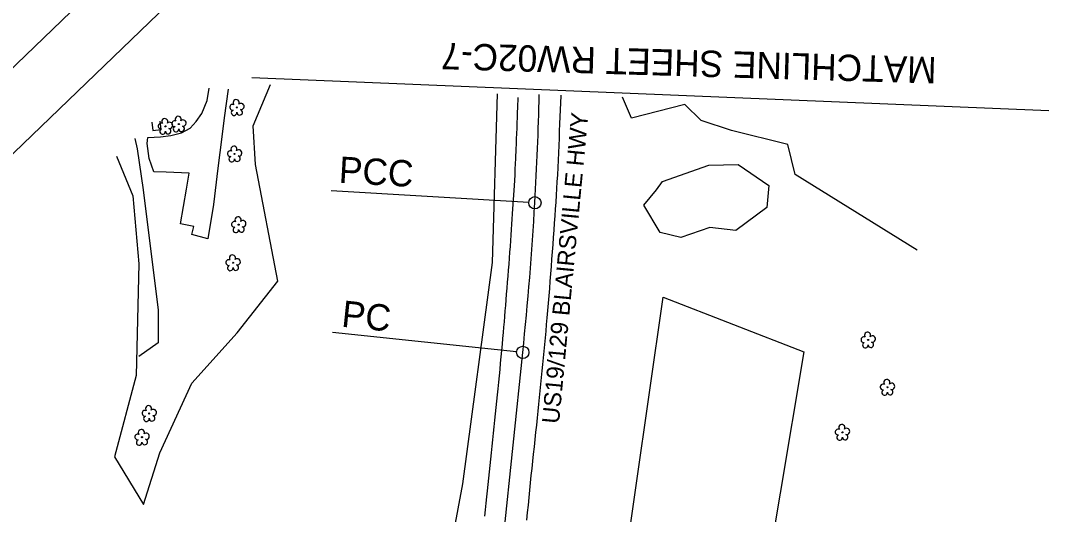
# Model space of a CAD drawing. Extents: x 473158 to 477500, y 500738 to 505114.
# Drawn here: x 474209 to 474845, y 504160 to 504459 of the extents above; entities that cross this region are included whole.
import ezdxf

# ---------------------------------------------------------------- set-up
doc = ezdxf.new("R2010")
doc.units = 0
for name, color, linetype in [('CTL Sheet Border CELL', 7, 'Continuous'), ('Exist Horizontal Alignment', 7, 'Continuous'), ('Exist Other Culture Area Outline', 7, 'Continuous'), ('Exist Roads EOP', 7, 'Continuous'), ('Exist Roads EOP Text', 7, 'Continuous'), ('Exist Roads Soil', 7, 'Continuous'), ('Exist Vegetation Hedge Row', 7, 'Continuous'), ('Exist Vegetation Tree CELL', 7, 'Continuous'), ('Exist Vegetation Woods Line', 7, 'Continuous'), ('Matchline', 7, 'Continuous'), ('Matchline Text', 7, 'Continuous'), ('Sheet Plot Border Outside CELL', 7, 'Continuous')]:
    doc.layers.add(name, color=color, linetype=linetype)

msp = doc.modelspace()

# ---------------------------------------------------------------- linework, layer by layer
at = {"layer": 'CTL Sheet Border CELL'}
msp.add_lwpolyline([(473224.2, 503436.31), (475527.63, 501042.56), (477203.24, 502654.95), (474899.8, 505048.7)], close=True, dxfattribs=at)
at = {"layer": 'Exist Horizontal Alignment'}
for p, q in [((474516.91, 504349.14), (474397.07, 504356.05)), ((474509.58, 504258.53), (474397.71, 504270.18)), ((474477.6, 503915.15), (474513.31, 504258.14))]:
    msp.add_line(p, q, dxfattribs=at)
for centre in [(474520.65, 504348.92), (474513.31, 504258.14)]:
    msp.add_circle(centre, 3.75, dxfattribs=at)
for centre, radius, start, end in [((472536.78, 504463.34), 1987.17, 356.69911, 358.59373), ((472549.42, 504462.61), 1974.51, 354.05611, 356.69911)]:
    msp.add_arc(centre, radius, start, end, dxfattribs=at)
at = {"layer": 'Exist Other Culture Area Outline'}
msp.add_lwpolyline([(474288.04, 504397.8), (474288.69, 504392.76), (474293.65, 504393.31), (474293.1, 504398.33)], dxfattribs=at)
at = {"layer": 'Exist Roads EOP'}
for points in [[(474490.23, 504158.74), (474490.63, 504162.67), (474491.02, 504166.55), (474491.42, 504170.39), (474491.82, 504174.23), (474492.22, 504178.05), (474492.62, 504181.87), (474493.02, 504185.69), (474493.43, 504189.53), (474493.84, 504193.39), (474494.25, 504197.27), (474494.66, 504201.18), (474495.08, 504205.1), (474495.51, 504209.03), (474495.94, 504212.99), (474496.37, 504216.93), (474496.79, 504220.82), (474497.2, 504224.68), (474497.59, 504228.49), (474497.98, 504232.29), (474498.37, 504236.11), (474498.75, 504239.96), (474499.13, 504243.84), (474499.5, 504247.72), (474499.87, 504251.59), (474500.24, 504255.44), (474500.6, 504259.28), (474500.95, 504263.03), (474501.28, 504266.64), (474501.59, 504270.1), (474501.88, 504273.41), (474502.15, 504276.66), (474502.43, 504279.95), (474502.7, 504283.27), (474502.97, 504286.63), (474503.24, 504290.04), (474503.52, 504293.51), (474503.81, 504297.06), (474504.1, 504300.68), (474504.4, 504304.34), (474504.69, 504307.99), (474504.97, 504311.64), (474505.24, 504315.3), (474505.51, 504318.92), (474505.77, 504322.46), (474506.01, 504325.92), (474506.25, 504329.31), (474506.48, 504332.62), (474506.71, 504335.85), (474506.94, 504339.01), (474507.17, 504342.1), (474507.58, 504348), (474507.92, 504353.54), (474508.24, 504359.31), (474508.42, 504362.51), (474508.6, 504365.92), (474508.78, 504369.36), (474508.94, 504372.62), (474509.09, 504375.72), (474509.36, 504381.53), (474509.48, 504384.53), (474509.6, 504387.65), (474509.72, 504390.87), (474509.83, 504394.13), (474509.94, 504397.36), (474510.05, 504400.55), (474510.16, 504403.71), (474510.26, 504406.8), (474510.42, 504412.71)], [(474536.38, 504414.23), (474536.36, 504413.74), (474536.2, 504409.54), (474536.04, 504405.31), (474535.87, 504401.04), (474535.69, 504396.75), (474535.51, 504392.42), (474535.32, 504388.06), (474535.13, 504383.65), (474534.93, 504379.2), (474534.73, 504374.7), (474534.53, 504370.24), (474534.31, 504365.89), (474534.09, 504361.66), (474533.86, 504357.53), (474533.62, 504353.45), (474533.36, 504349.31), (474533.07, 504345.12), (474532.77, 504340.89), (474532.45, 504336.61), (474532.13, 504332.29), (474531.81, 504327.92), (474531.49, 504323.52), (474531.17, 504319.09), (474530.84, 504314.67), (474530.51, 504310.24), (474530.16, 504305.82), (474529.81, 504301.39), (474529.45, 504296.92), (474529.08, 504292.44), (474528.7, 504287.92), (474528.32, 504283.47), (474527.95, 504279.15), (474527.58, 504274.98), (474527.23, 504270.94), (474526.87, 504266.97), (474526.5, 504262.97), (474526.11, 504258.95), (474525.72, 504254.91), (474525.32, 504250.87), (474524.92, 504246.84), (474524.51, 504242.84), (474524.11, 504238.86), (474523.71, 504234.86), (474523.31, 504230.81), (474522.9, 504226.71), (474522.49, 504222.55), (474522.06, 504218.33), (474521.61, 504214.04), (474521.14, 504209.68), (474520.64, 504205.25), (474520.14, 504200.8), (474519.66, 504196.4), (474519.19, 504192.03), (474518.74, 504187.71), (474518.3, 504183.38), (474517.86, 504178.99), (474517.41, 504174.55), (474516.97, 504170.06), (474516.52, 504165.52), (474516.07, 504160.92), (474515.61, 504156.26)]]:
    msp.add_lwpolyline(points, dxfattribs=at)
at = {"layer": 'Exist Roads Soil'}
msp.add_lwpolyline([(474334.45, 504417.79), (474331.99, 504400.48), (474330.54, 504388.83), (474328.19, 504369.97), (474325.56, 504347.93), (474322.02, 504327.01), (474312.44, 504329.74), (474313.58, 504334.59), (474305.58, 504336.12), (474309.15, 504357.23), (474310.84, 504366.79), (474296.71, 504367.46), (474289.31, 504367.76), (474286.56, 504375.81), (474285.17, 504384.8), (474285.62, 504388.51), (474293.35, 504388.81), (474299.53, 504389.75), (474306.15, 504391.41), (474311.32, 504394.14), (474314.94, 504398.12), (474318.41, 504403.11), (474321.73, 504410.94), (474322.98, 504418.4)], dxfattribs=at)
at = {"layer": 'Exist Vegetation Hedge Row'}
for points in [[(474277.71, 504387.85), (474279.27, 504381.67), (474282.87, 504356.8), (474291.91, 504283.76), (474291.88, 504263.97), (474280.29, 504255.68)], [(474662.67, 504359.3), (474661.6, 504346.12), (474642.68, 504332.11), (474626.9, 504333.83), (474609.27, 504327.8), (474596.83, 504330.81), (474586.91, 504347.4), (474594.44, 504356.75), (474598.21, 504361.79), (474626.39, 504371.72), (474644.05, 504372.16), (474662.67, 504359.3)]]:
    msp.add_lwpolyline(points, dxfattribs=at)
at = {"layer": 'Exist Vegetation Tree CELL'}
for p, q in [((474339.7, 504406.73), (474339.7, 504406.73)), ((474296.32, 504395.26), (474296.32, 504395.26)), ((474304.49, 504396.67), (474304.49, 504396.67)), ((474338.32, 504378.57), (474338.32, 504378.57)), ((474340.79, 504335.64), (474340.79, 504335.64)), ((474337.41, 504312.49), (474337.41, 504312.49)), ((474723.03, 504265.65), (474723.03, 504265.65)), ((474734.73, 504236.97), (474734.73, 504236.97)), ((474286.5, 504221.07), (474286.5, 504221.07)), ((474707.4, 504209.62), (474707.4, 504209.62)), ((474282.11, 504206.67), (474282.11, 504206.67))]:
    msp.add_line(p, q, dxfattribs=at)
for centre in [(474339.7, 504406.73), (474296.32, 504395.26), (474304.49, 504396.67), (474338.32, 504378.57), (474340.79, 504335.64), (474337.41, 504312.49), (474723.03, 504265.65), (474734.73, 504236.97), (474286.5, 504221.07), (474707.4, 504209.62), (474282.11, 504206.67)]:
    msp.add_circle(centre, 0.326, dxfattribs=at)
for centre, radius, start, end in [((474339.32, 504409.61), 1.86, 330.16508, 219.71335), ((474337.1, 504406.89), 1.73, 62.66361, 279.3457), ((474338, 504403.61), 1.69, 111.56708, 6.23104), ((474341.38, 504403.83), 1.7, 181.28216, 74.55999), ((474342.25, 504407.32), 1.9, 257.1011, 134.19993), ((474295.94, 504398.13), 1.86, 330.16508, 219.71335), ((474301.89, 504396.82), 1.73, 62.66361, 279.3457), ((474304.11, 504399.54), 1.86, 330.16508, 219.71335), ((474307.04, 504397.26), 1.9, 257.1011, 134.19993), ((474293.71, 504395.41), 1.73, 62.66361, 279.3457), ((474294.62, 504392.14), 1.69, 111.56708, 6.23104), ((474297.99, 504392.36), 1.7, 181.28216, 74.55999), ((474298.87, 504395.85), 1.9, 257.1011, 134.19993), ((474302.79, 504393.55), 1.69, 111.56708, 6.23104), ((474306.16, 504393.77), 1.7, 181.28216, 74.55999), ((474335.72, 504378.72), 1.73, 62.66361, 279.3457), ((474337.94, 504381.44), 1.86, 330.16508, 219.71335), ((474340.87, 504379.16), 1.9, 257.1011, 134.19993), ((474336.62, 504375.45), 1.69, 111.56708, 6.23104), ((474340, 504375.67), 1.7, 181.28216, 74.55999), ((474338.19, 504335.79), 1.73, 62.66361, 279.3457), ((474340.41, 504338.51), 1.86, 330.16508, 219.71335), ((474343.34, 504336.22), 1.9, 257.1011, 134.19993), ((474339.09, 504332.51), 1.69, 111.56708, 6.23104), ((474342.47, 504332.74), 1.7, 181.28216, 74.55999), ((474337.02, 504315.37), 1.86, 330.16508, 219.71335), ((474334.8, 504312.65), 1.73, 62.66361, 279.3457), ((474335.7, 504309.37), 1.69, 111.56708, 6.23104), ((474339.08, 504309.59), 1.7, 181.28216, 74.55999), ((474339.96, 504313.08), 1.9, 257.1011, 134.19993), ((474720.42, 504265.81), 1.73, 62.66361, 279.3457), ((474722.64, 504268.52), 1.86, 330.16508, 219.71335), ((474725.58, 504266.24), 1.9, 257.1011, 134.19993), ((474721.33, 504262.53), 1.69, 111.56708, 6.23104), ((474724.7, 504262.75), 1.7, 181.28216, 74.55999), ((474734.34, 504239.84), 1.86, 330.16508, 219.71335), ((474737.28, 504237.56), 1.9, 257.1011, 134.19993), ((474732.12, 504237.12), 1.73, 62.66361, 279.3457), ((474733.02, 504233.85), 1.69, 111.56708, 6.23104), ((474736.4, 504234.07), 1.7, 181.28216, 74.55999), ((474283.9, 504221.23), 1.73, 62.66361, 279.3457), ((474286.12, 504223.95), 1.86, 330.16508, 219.71335), ((474289.05, 504221.66), 1.9, 257.1011, 134.19993), ((474284.8, 504217.95), 1.69, 111.56708, 6.23104), ((474288.17, 504218.17), 1.7, 181.28216, 74.55999), ((474707.02, 504212.49), 1.86, 330.16508, 219.71335), ((474279.5, 504206.83), 1.73, 62.66361, 279.3457), ((474281.72, 504209.55), 1.86, 330.16508, 219.71335), ((474284.66, 504207.26), 1.9, 257.1011, 134.19993), ((474704.8, 504209.77), 1.73, 62.66361, 279.3457), ((474705.7, 504206.49), 1.69, 111.56708, 6.23104), ((474709.07, 504206.72), 1.7, 181.28216, 74.55999), ((474709.95, 504210.2), 1.9, 257.1011, 134.19993), ((474280.4, 504203.55), 1.69, 111.56708, 6.23104), ((474283.78, 504203.77), 1.7, 181.28216, 74.55999)]:
    msp.add_arc(centre, radius, start, end, dxfattribs=at)
at = {"layer": 'Exist Vegetation Woods Line'}
for points in [[(474266.67, 504377.23), (474276.48, 504353.12), (474280.16, 504311.93), (474278.49, 504244.03), (474265.48, 504194.69), (474283.11, 504165.74), (474292.94, 504197.23), (474312.45, 504239.54), (474339.82, 504269.94), (474364.61, 504301.42), (474351.03, 504372.12), (474349.56, 504395.67), (474360.04, 504420.69)], [(474497.83, 504414.91), (474494.78, 504312.62)], [(474639.97, 504392.83), (474621.7, 504398.72), (474611.75, 504408.6), (474579.32, 504400.15), (474573.82, 504413.02)], [(474752.8, 504320.13), (474678.73, 504366.13), (474674.27, 504384.21), (474639.97, 504392.83)], [(474494.78, 504312.62), (474476.79, 504178.44), (474459.77, 504087.31), (474441.83, 503933.16), (474440.33, 503857.37), (474437.89, 503709.04), (474417.41, 503659.72)], [(474598.56, 504291.71), (474683.89, 504258.46), (474655.17, 504086.99), (474612.22, 504056.82), (474565.4, 504060.3), (474598.56, 504291.71)]]:
    msp.add_lwpolyline(points, dxfattribs=at)
at = {"layer": 'Matchline'}
msp.add_line((474348.85, 504424.83), (474832.78, 504404.9), dxfattribs=at)
at = {"layer": 'Sheet Plot Border Outside CELL'}
msp.add_lwpolyline([(477499.57, 502426.85), (474913.58, 505114.22), (473158.19, 503425.06), (475744.18, 500737.68)], close=True, dxfattribs=at)

# ---------------------------------------------------------------- texts
at = {"layer": 'Exist Horizontal Alignment'}
for s, rotation, p in [('PCC', 356.69911, (474401.35, 504361.04)), ('PC', 354.05611, (474402.81, 504273.77))]:
    msp.add_text(s, height=16, rotation=rotation, dxfattribs=at).set_placement(p)
at = {"layer": 'Exist Roads EOP Text'}
msp.add_text('US19/129 BLAIRSVILLE HWY', height=10.4, rotation=84.5688, dxfattribs=at).set_placement((474535.29, 504214.54))
at = {"layer": 'Matchline Text'}
msp.add_text('MATCHLINE SHEET RW02C-7', height=16, rotation=178.32958, dxfattribs=at).set_placement((474764.75, 504437.22))

doc.saveas('drawing.dxf')
